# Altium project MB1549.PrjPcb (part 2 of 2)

## Sheet POWER_BOARD.SchDoc: POWER_BOARD
size A4; Date: Not used; ApprovedBy: Not used; CheckedBy: Not used; Author: Not used; CompanyName: STMicroelectronics; DrawnBy: Not used; Engineer: Not used; Organization: Not used; Address1: Not used; Address2: Not used; Address3: Not used; Address4: Not used; DocumentNumber: 7; Revision: Not used; SheetNumber: 7; SheetTotal: 8
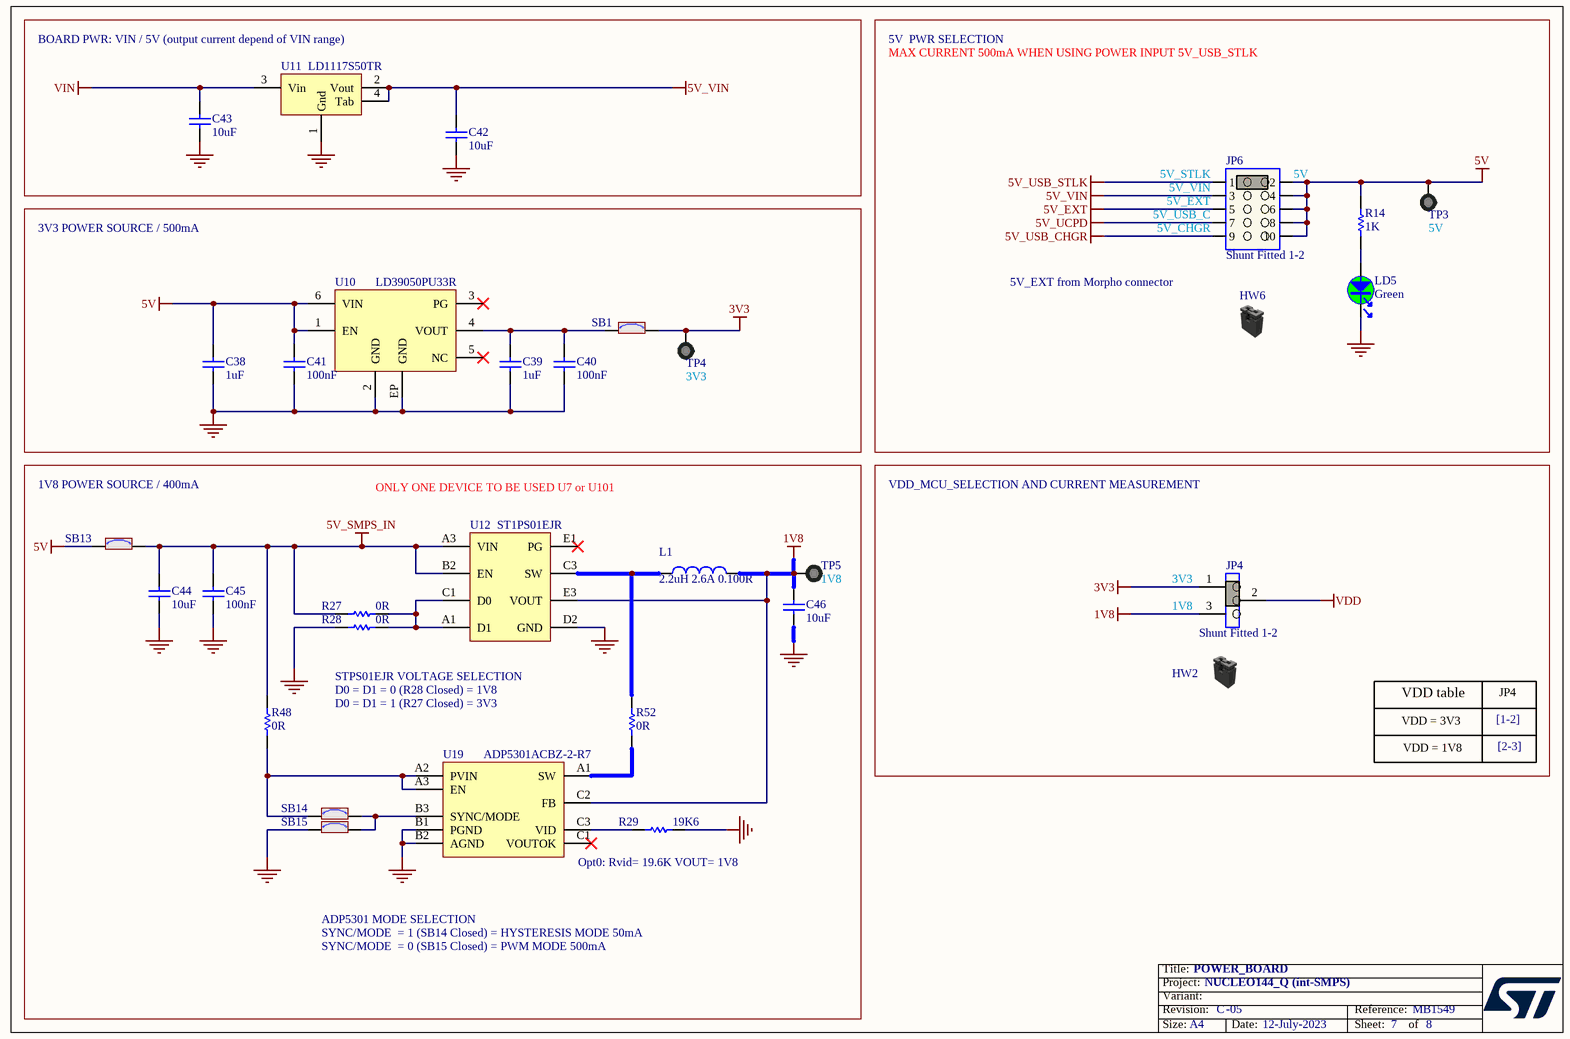
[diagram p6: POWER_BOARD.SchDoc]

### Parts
C38  value 1uF  [C0603]  (hidden comment: Capacitor)
C39  value 1uF  [C0603]  (hidden comment: Capacitor)
C40  value 100nF  [C0402]
C41  value 100nF  [C0402]
C42  value 10uF  [C0805]
C43  value 10uF  [C0805]
C44  value 10uF  [C0603]
C45  value 100nF  [C0402]
C46  value 10uF  [C0603]
HW2  (no value)  (mechanical)
HW6  (no value)  (mechanical)
JP4  value Shunt Fitted 1-2  [CON_SAMTEC_TSW-103-07-F-S]
JP6  value Shunt Fitted 1-2  [CON_SAMTEC_TSW-105-07-X-D]
L1  value 2.2uH 2.6A 0.100R  [IND_TDK_VLS252010HBX-1]
LD5  value Green  [LED_0603_GREEN]  (hidden comment: LED_green)
R14  value 1K  [R0603]
R27  value 0R  [R0603]
R28  value 0R  [R0603]
R29  value 19K6  [R0603]
R48  value 0R  [R0603]
R52  value 0R  [R0603]
SB1  (no value)  [SOLDER-BRIDGE_R0603-0R]
SB13  (no value)  [SOLDER-BRIDGE_R0603-0R]
SB14  (no value)  [SOLDER-BRIDGE_R0603-0R]
SB15  (no value)  [SOLDER-BRIDGE_R0603-0R]
TP3  Test_Point_PTH_1mm_2mm  [TP_PTH_1MM_2MM]  (value not drawn)  (no BOM)
TP4  Test_Point_PTH_1mm_2mm  [TP_PTH_1MM_2MM]  (value not drawn)  (no BOM)
TP5  Test_Point_PTH_1mm_2mm  [TP_PTH_1MM_2MM]  (value not drawn)  (no BOM)
U10  value LD39050PU33R  [ICC_DFN6-EPAD_3X3_P095]
U11  value LD1117S50TR  [REG_SOT223-TAB]
U12  value ST1PS01EJR  [ICC_FLIP-CHIP-BGA8_1P11X1P41_P040]
U19  value ADP5301ACBZ-2-R7  [ICC_WLCSP9_1P65X1P87_P050]

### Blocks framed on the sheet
BOARD PWR: VIN / 5V (output current depend of VIN range): C42 C43 U11
VDD table: HW2 JP4

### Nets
1V8: C46.2 JP4.3 L1.2 TP5.1 U12.E3(VOUT) U19.C2(FB)
3V3: JP4.1 SB1.2 TP4.1
5V: C38.2 C41.2 JP6.2 JP6.4 JP6.6 JP6.8 JP6.10 R14.2 SB13.1 TP3.1 U10.1(EN) U10.6(VIN)
5V_EXT: JP6.5
5V_SMPS_IN: C44.2 C45.2 R27.2 R48.1 SB13.2 U12.A3(VIN) U12.B2(EN)
5V_UCPD: JP6.7
5V_USB_CHGR: JP6.9
5V_USB_STLK: JP6.1
5V_VIN: C42.2 JP6.3 U11.2(Vout) U11.4(Tab)
GND: C38.1 C39.1 C40.1 C41.1 C42.1 C43.1 C44.1 C45.1 C46.1 LD5.2 R28.2 R29.2 SB15.1 U10.2(GND) U10.EP(GND) U11.1(Gnd) U12.D2(GND) U19.B1(PGND) U19.B2(AGND)
VDD: JP4.2
VIN: C43.2 U11.3(Vin)
NetC39_2: C39.2 C40.2 SB1.1 U10.4(VOUT)
NetL1_1: L1.1 R52.1 U12.C3(SW)
NetLD5_1: LD5.1 R14.1
NetR27_1: R27.1 R28.1 U12.A1(D1) U12.C1(D0)
NetR29_1: R29.1 U19.C3(VID)
NetR48_2: R48.2 SB14.1 U19.A2(PVIN) U19.A3(EN)
NetR52_2: R52.2 U19.A1(SW)
NetSB14_2: SB14.2 SB15.2 U19.B3(SYNC/MODE)

Not connected (* = marked no-connect by the designer): U10 3(PG)* 5(NC)*; U12 E1(PG)*; U19 C1(VOUTOK)*

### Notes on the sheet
- 5V  PWR SELECTION
- MAX CURRENT 500mA WHEN USING POWER INPUT 5V_USB_STLK
- (near JP6) 5V_STLK
- (near JP6) 5V
- 3V3 POWER SOURCE / 500mA
- (near JP6) 5V_CHGR
- (near JP6) 5V_VIN
- (near JP6) 5V_EXT
- (near JP6) 5V_USB_C
- (near TP3) 5V
- 5V_EXT from Morpho connector
- (near TP4) 3V3
- 1V8 POWER SOURCE / 400mA
- ONLY ONE DEVICE TO BE USED U7 or U101
- VDD_MCU_SELECTION AND CURRENT MEASUREMENT
- (near TP5) 1V8
- (near JP4) 3V3
- 1V8
- STPS01EJR VOLTAGE SELECTION
  D0 = D1 = 0 (R28 Closed) = 1V8
  D0 = D1 = 1 (R27 Closed) = 3V3
- [1-2]
- JP4
- VDD = 3V3
- VDD = 1V8
- [2-3]
- Opt0: Rvid= 19.6K VOUT= 1V8
- ADP5301 MODE SELECTION
  SYNC/MODE  = 1 (SB14 Closed) = HYSTERESIS MODE 50mA
  SYNC/MODE  = 0 (SB15 Closed) = PWM MODE 500mA

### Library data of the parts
C38 C39 = MCD-00010: Capacitor, MLCC, 1uF, 16V, X5R, 10%, 0603, T=0,8mm; Manufacturer_Part_Number: CC0603KRX5R7BB105; Manufacturer: YAGEO; Provided_By: SUBCO
C40 C41 C45 = MCD-00006: Capacitor, MLCC, 100nF, 16V, X7R, 10%, 0402, T=0.5mm; Manufacturer_Part_Number: CC0402KRX7R7BB104; Manufacturer: YAGEO; Alternate_Manufacturer_Part_Number: GCM155R71C104KA55D; Alternate_Manufacturer: MURATA; Provided_By: SUBCO; ECCN_US: EAR99; ECCN_EU: NEC
C42 C43 = MCD-00014: Capacitor, MLCC, 10uF, 25V, X5R, 10%, 0805, T=0,85mm; Manufacturer_Part_Number: CC0805KRX5R8BB106; Manufacturer: YAGEO; Provided_By: Subcon; Initial_Board_Reference: MB1274
C44 C46 = MCD-00243: Capacitor, MLCC, 10uF, 6V3, X5R, 10%, 0603, T=0,8mm; Manufacturer_Part_Number: CC0603KRX5R5BB106; Manufacturer: YAGEO; Provided_By: Subcon; Initial_Board_Reference: MB1319
HW2 HW6 = MCD-00043: SHUNT 2.54mm BLACK; Manufacturer_Part_Number: SNT-100-BK-G; Manufacturer: SAMTEC; Part_Type: Mechanical; Provided_By: Subcon; Initial_Board_Reference: MB1274
JP4 = MCD-00684: Header, 3x1, 2,54mm, VR, TH, Height 5.84mm/2.54mm - Shunt Fitted 1-2 by default; Part_Type: Connector; Manufacturer_Part_Number: TSW-103-07-F-S; Manufacturer: SAMTEC; Provided_By: Subcon; Initial_Board_Reference: MB1331
JP6 = MCD-01203: Header, 5x2, 2,54mm, VR, TH, Height 5.84mm/2.54mm - Shunt Fitted 1-2; Part_Type: Connector; Manufacturer_Part_Number: TSW-105-07-x-D; Manufacturer: SAMTEC; Provided_By: Subcon; Initial_Board_Reference: Mb1372
L1 = MCD-00240: FIXED IND 2.2UH 2.6A 100 mOHM 20% SMD; Manufacturer_Part_Number: VLS252010HBX-2R2M-1; Manufacturer: TDK; Provided_By: Subcon; Initial_Board_Reference: MB1319
LD5 = MCD-02900: LED, Green, 2V, 20mA, 0603; Part_Type: Display; Part_Preference: Recommended; Manufacturer: EVERLIGHT; Manufacturer_Part_Number: 19-213SYGC/S530-E2/5T; Full_Alternate_Internal_Part_Number: MCD-00320; Partial_Alternate_Internal_Part_Number: MCD-00050; Component_Country_Of_Origin: China; ShowFields: YES; ID: 5016
R14 = MCD-00070: Resistor,1K,0603,1%,1/10W; Manufacturer_Part_Number: RC0603FR-071KL; Manufacturer: YAGEO; Provided_By: Subcon; Initial_Board_Reference: MB1274
R27 R28 R48 R52 = MCD-00056: Resistor,0R,0603,5%,1/10W; Manufacturer_Part_Number: RC0603JR-070RL; Manufacturer: YAGEO; Provided_By: subcon; Initial_Board_Reference: MB1274
R29 = MCD-00242: Resistor,19K6,0603,1%,1/10W; Manufacturer_Part_Number: RC0603FR-0719K6L; Manufacturer: YAGEO; Provided_By: Subcon; Initial_Board_Reference: MB1319
SB1 SB13-SB15 = MCD-00071: Solder Bridge ON; Part_Type: Mechanical; Provided_By: Subcon; Initial_Board_Reference: MB1274
TP3-TP5 = MCD-01506: Test Point trought hole 1mm/2mm; Part_Type: Mechanical; Value: TP
U10 = MCD-00215: Low quiescent current and low noise voltage regulators; Manufacturer: STMICROELECTRONICS; Part_Type: IC; ECCN_US: EAR99; ECCN_EU: NEC; Provided_By: Subcon; Initial_Board_Reference: MB1319
U11 = MCD-00088: IC REG LDO 5V 0.8A SOT223; Manufacturer: STMICROELECTRONICS; ECCN_US: EAR99; ECCN_EU: NEC; Provided_By: Subcon; Initial_Board_Reference: MB1274
U12 = MCD-00228: 400mA Nano-Quiescent Step down converter; Manufacturer: STMICROELECTRONICS; Part_Type: IC; ECCN_US: EAR99; ECCN_EU: NEC; Provided_By: Subcon; Initial_Board_Reference: MB1319
U19 = MCD-00226: UL Step down regulator: Opt0; Manufacturer: ANALOG DEVICES; Part_Type: IC; ECCN_US: EAR99; ECCN_EU: NEC; Provided_By: Subcon; Initial_Board_Reference: MB1319

## Sheet ST_LINK_V3E.SchDoc: STLINK_V3E
size A3; Date: Not used; ApprovedBy: Not used; CheckedBy: Not used; Author: Not used; CompanyName: STMicroelectronics; DrawnBy: Not used; Engineer: Not used; Organization: Not used; Address1: Not used; Address2: Not used; Address3: Not used; Address4: Not used; DocumentNumber: 8; Revision: Not used; SheetNumber: 8; SheetTotal: 8
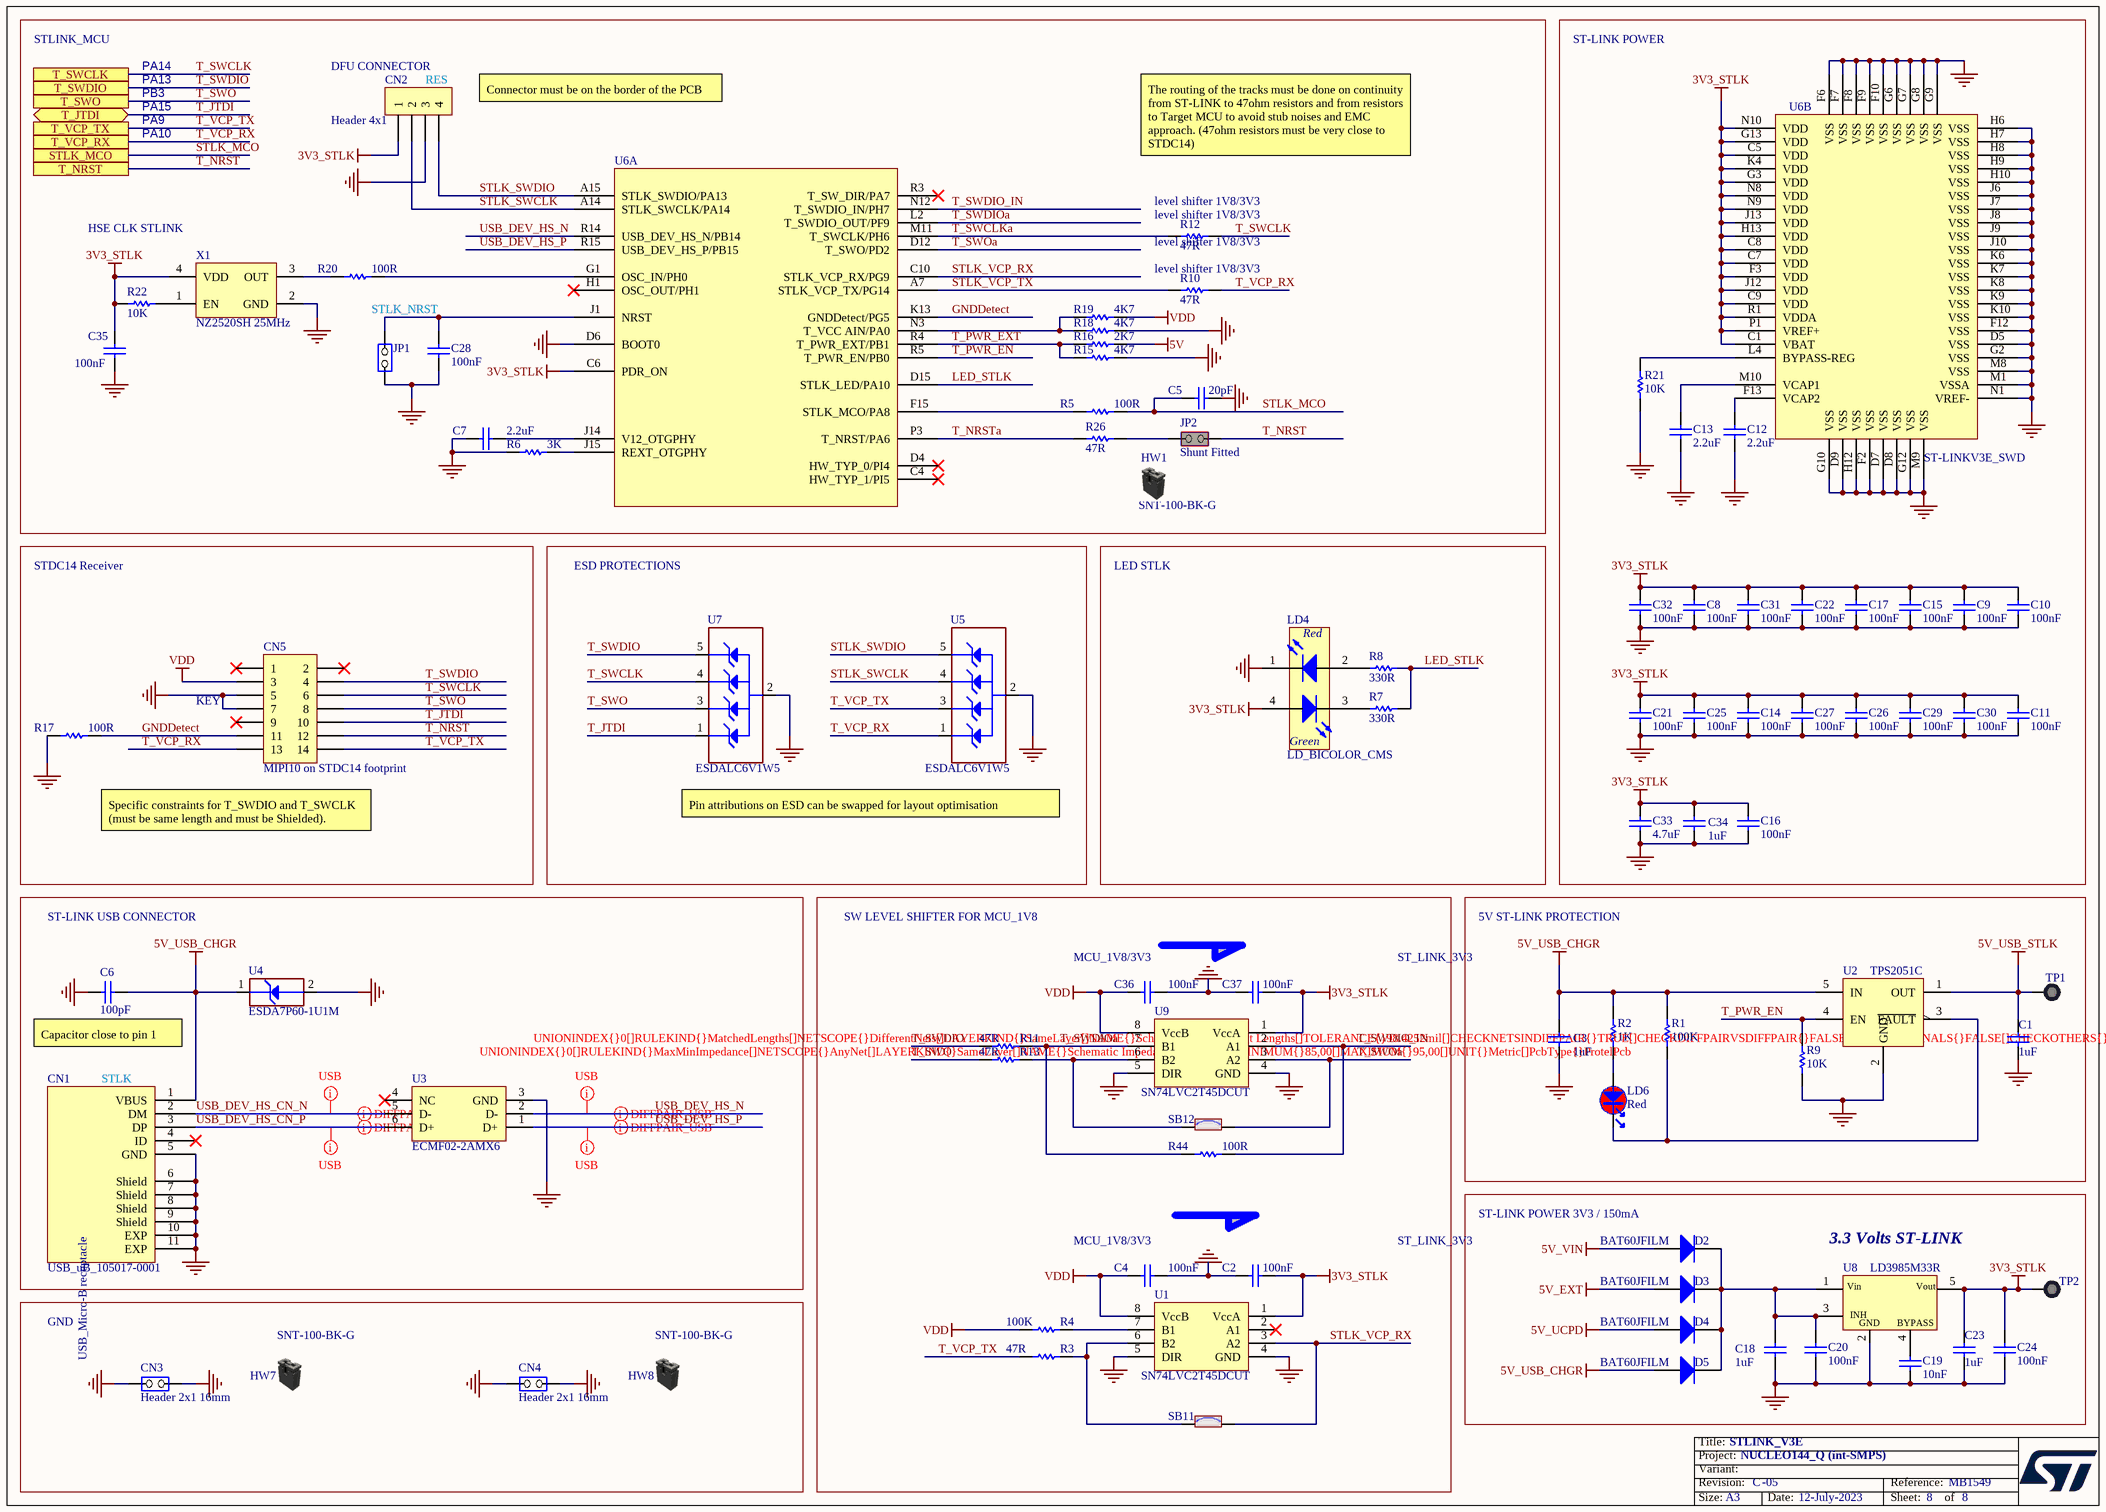
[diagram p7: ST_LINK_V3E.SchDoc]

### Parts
C1  value 1uF  [C0603]  (hidden comment: Capacitor)
C2  value 100nF  [C0402]
C3  value 1uF  [C0603]  (hidden comment: Capacitor)
C4  value 100nF  [C0402]
C5  value 20pF  [C0402]  (hidden comment: Capacitor)
C6  value 100pF  [C0402]  (hidden comment: Capacitor)
C7  value 2.2uF  [C0603]  (hidden comment: Capacitor)
C8  value 100nF  [C0402]
C9  value 100nF  [C0402]
C10  value 100nF  [C0402]
C11  value 100nF  [C0402]
C12  value 2.2uF  [C0603]  (hidden comment: Capacitor)
C13  value 2.2uF  [C0603]  (hidden comment: Capacitor)
C14  value 100nF  [C0402]
C15  value 100nF  [C0402]
C16  value 100nF  [C0402]
C17  value 100nF  [C0402]
C18  value 1uF  [C0603]  (hidden comment: Capacitor)
C19  value 10nF  [C0402]  (hidden comment: Capacitor)
C20  value 100nF  [C0402]
C21  value 100nF  [C0402]
C22  value 100nF  [C0402]
C23  value 1uF  [C0603]  (hidden comment: Capacitor)
C24  value 100nF  [C0402]
C25  value 100nF  [C0402]
C26  value 100nF  [C0402]
C27  value 100nF  [C0402]
C28  value 100nF  [C0402]
C29  value 100nF  [C0402]
C30  value 100nF  [C0402]
C31  value 100nF  [C0402]
C32  value 100nF  [C0402]
C33  value 4.7uF  [C0603]  (hidden comment: Capacitor)
C34  value 1uF  [C0603]  (hidden comment: Capacitor)
C35  value 100nF  [C0402]
C36  value 100nF  [C0402]
C37  value 100nF  [C0402]
CN1  value USB_uB_105017-0001  [CON_USBMICROB_MOLEX_105017-0001_H2P90]  (hidden comment: USB_uB_105017.0001)
CN2  Header 4x1  [CON_SAMTEC_TSW-104-07-G-S]
CN3  value Header 2x1 16mm  [CON_SAMTEC_TSW-102-09-X-S]  (hidden comment: Jumper_Header 2x1)
CN4  value Header 2x1 16mm  [CON_SAMTEC_TSW-102-09-X-S]  (hidden comment: Jumper_Header 2x1)
CN5  value MIPI10 on STDC14 footprint  [CON_STDC14_Receiver_MEDIUM_WITH_MIPI10_3D]  (hidden comment: Header 7x2)
D2  BAT60JFILM  [DIO_SOD323]
D3  BAT60JFILM  [DIO_SOD323]
D4  BAT60JFILM  [DIO_SOD323]
D5  BAT60JFILM  [DIO_SOD323]
HW1  value SNT-100-BK-G  (hidden comment: Shunt Black 2.54mm)  (mechanical)
HW7  value SNT-100-BK-G  (hidden comment: Shunt Black 2.54mm)  (mechanical)
HW8  value SNT-100-BK-G  (hidden comment: Shunt Black 2.54mm)  (mechanical)
JP1  Jumper_Header 2x1  [CON_SAMTEC_TSW-102-07-G-S]  (value not drawn)
JP2  value Shunt Fitted  [CON_SAMTEC_TSW-102-07-G-S]  (hidden comment: Jumper_Header 2x1 Fitted)
LD4  LD_BICOLOR_CMS  [LED_BI-GR_HSMF-A201-A00J1]
LD6  value Red  [LED_0603_RED]  (hidden comment: LED_red)
R1  value 100K  [R0603]  (hidden comment: Resistor)
R2  value 1K  [R0603]  (hidden comment: Resistor)
R3  value 47R  [R0402]  (hidden comment: Resistor)
R4  value 100K  [R0603]  (hidden comment: Resistor)
R5  value 100R  [R0402]  (hidden comment: Resistor)
R6  value 3K  [R0402]  (hidden comment: Resistor)
R7  value 330R  [R0603]  (hidden comment: Resistor)
R8  value 330R  [R0603]  (hidden comment: Resistor)
R9  value 10K  [R0402]  (hidden comment: Resistor)
R10  value 47R  [R0402]  (hidden comment: Resistor)
R11  value 47R  [R0402]  (hidden comment: Resistor)
R12  value 47R  [R0402]  (hidden comment: Resistor)
R13  value 47R  [R0402]  (hidden comment: Resistor)
R15  value 4K7  [R0402]  (hidden comment: Resistor)
R16  value 2K7  [R0402]  (hidden comment: Resistor)
R17  value 100R  [R0402]  (hidden comment: Resistor)
R18  value 4K7  [R0402]  (hidden comment: Resistor)
R19  value 4K7  [R0402]  (hidden comment: Resistor)
R20  value 100R  [R0402]  (hidden comment: Resistor)
R21  value 10K  [R0402]  (hidden comment: Resistor)
R22  value 10K  [R0402]  (hidden comment: Resistor)
R26  value 47R  [R0402]  (hidden comment: Resistor)
R44  value 100R  [R0402]  (hidden comment: Resistor)
SB11  SB_ON  [SOLDER-BRIDGE_R0603-0R]  (value not drawn)
SB12  SB_ON  [SOLDER-BRIDGE_R0603-0R]  (value not drawn)
TP1  Test_Point_PTH_1mm_2mm  [TP_PTH_1MM_2MM]  (value not drawn)  (no BOM)
TP2  Test_Point_PTH_1mm_2mm  [TP_PTH_1MM_2MM]  (value not drawn)  (no BOM)
U1  SN74LVC2T45DCUT  [ICC_VSSOP8_DCU_R-PDSO-G8_2X2P30_P050]
U2  TPS2051C  [MOS_SOT23-5L]
U3  ECMF02-2AMX6  [ESD_QFN-6L_1P7X1P5_P050]
U4  value ESDA7P60-1U1M  [ESD_QFN2_1P6X1_P125]  (hidden comment: ESD-TRANSIL)
U5  ESDALC6V1W5  [ESD_SOT323-5L]
U6  ST-LINKV3E_SWD  [ICC_UFBGA201_176+25_10X10_P065]  (parts A,B of 2)
U7  ESDALC6V1W5  [ESD_SOT323-5L]
U8  LD3985M33R  [REG_SOT23-5L]
U9  SN74LVC2T45DCUT  [ICC_VSSOP8_DCU_R-PDSO-G8_2X2P30_P050]
X1  value NZ2520SH 25MHz  [OSC_NDK_NZ2520SB_4P]  (hidden comment: OSCILLATOR_4_PINS)

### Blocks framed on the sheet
ST-LINK POWER: C8-C17 C21 C22 C25-C27 C29-C34 R21 U6
ESD PROTECTIONS: U5 U7
LED STLK: LD4 R7 R8
5V ST-LINK PROTECTION: C1 C3 LD6 R1 R2 R9 TP1 U2
3.3 Volts ST-LINK: C18-C20 C23 C24 D2-D5 TP2 U8
GND: CN3 CN4 HW7 HW8

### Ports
STLK_MCO, T_JTDI (bidir), T_NRST, T_SWCLK, T_SWDIO, T_SWO, T_VCP_RX, T_VCP_TX

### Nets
3V3_STLK: C2.2 C8.2 C9.2 C10.2 C11.2 C14.2 C15.2 C16.2 C17.2 C21.2 C22.2 C23.2 C24.2 C25.2 C26.2 C27.2 C29.2 C30.2 C31.2 C32.2 C33.2 C34.2 C35.2 C37.2 CN2.1 LD4.4(YellowGreen_anode) R22.2 TP2.1 U1.1(VccA) U6.C1(VBAT) U6.C5(VDD) U6.C6(PDR_ON) U6.C7(VDD) U6.C8(VDD) U6.C9(VDD) U6.F3(VDD) U6.G3(VDD) U6.G13(VDD) U6.H13(VDD) U6.J12(VDD) U6.J13(VDD) U6.K4(VDD) U6.N8(VDD) U6.N9(VDD) U6.N10(VDD) U6.P1(VREF+) U6.R1(VDDA) U8.5(Vout) U9.1(VccA) X1.4(VDD)
5V: R16.1
5V_EXT: D3.1(A)
5V_UCPD: D4.1(A)
5V_USB_CHGR: C3.2 C6.2 CN1.1(VBUS) D5.1(A) R1.2 R2.2 U2.5(IN) U4.1(IO1)
5V_USB_STLK: C1.2 TP1.1 U2.1(OUT)
5V_VIN: D2.1(A)
GND: C1.1 C2.1 C3.1 C4.2 C5.1 C6.1 C7.1 C8.1 C9.1 C10.1 C11.1 C12.1 C13.1 C14.1 C15.1 C16.1 C17.1 C18.1 C19.1 C20.1 C21.1 C22.1 C23.1 C24.1 C25.1 C26.1 C27.1 C28.1 C29.1 C30.1 C31.1 C32.1 C33.1 C34.1 C35.1 C36.2 C37.1 CN1.5(GND) CN1.6(Shield) CN1.7(Shield) CN1.8(Shield) CN1.9(Shield) CN1.10(EXP) CN1.11(EXP) CN2.3 CN3.1(COMMON) CN3.2(NO) CN4.1(COMMON) CN4.2(NO) CN5.5 CN5.7 JP1.1(COMMON) LD4.1(RED_cathode) R6.1 R9.2 R15.1 R17.1 R18.2 R21.1 U1.4(GND) U1.5(DIR) U2.2(GND) U3.3(GND) U4.2(GND) U5.2(GND) U6.D5(VSS) U6.D6(BOOT0) U6.D7(VSS) U6.D8(VSS) U6.D9(VSS) U6.F2(VSS) U6.F6(VSS) U6.F7(VSS) U6.F8(VSS) U6.F9(VSS) U6.F10(VSS) U6.F12(VSS) U6.G2(VSS) U6.G6(VSS) U6.G7(VSS) U6.G8(VSS) U6.G9(VSS) U6.G10(VSS) U6.G12(VSS) U6.H6(VSS) U6.H7(VSS) U6.H8(VSS) U6.H9(VSS) U6.H10(VSS) U6.H12(VSS) U6.J6(VSS) U6.J7(VSS) U6.J8(VSS) U6.J9(VSS) U6.J10(VSS) U6.K6(VSS) U6.K7(VSS) U6.K8(VSS) U6.K9(VSS) U6.K10(VSS) U6.M1(VSSA) U6.M8(VSS) U6.M9(VSS) U6.N1(VREF-) U7.2(GND) U8.2(GND) U9.4(GND) U9.5(DIR) X1.2(GND)
VDD: C4.1 C36.1 CN5.3 R4.2 R19.2 U1.8(VccB) U9.8(VccB)
GNDDetect: CN5.11 R17.2 U6.K13(GNDDetect/PG5)
LED_STLK: R7.2 R8.2 U6.D15(STLK_LED/PA10)
STLK_MCO: C5.2 R5.2 ; port STLK_MCO
STLK_SWCLK: CN2.2 U5.4(IO3) U6.A14(STLK_SWCLK/PA14)
STLK_SWDIO: CN2.4 U5.5(IO4) U6.A15(STLK_SWDIO/PA13)
STLK_VCP_RX: SB11.1 U1.3(A2) U6.C10(STLK_VCP_RX/PG9)
STLK_VCP_TX: R10.1 U6.A7(STLK_VCP_TX/PG14)
T_JTDI: CN5.10 U7.1(IO1) ; port T_JTDI
T_NRST: CN5.12 JP2.2(NO) ; port T_NRST
T_NRSTa: R26.1 U6.P3(T_NRST/PA6)
T_PWR_EN: R9.1 U2.4(EN) U6.R5(T_PWR_EN/PB0)
T_PWR_EXT: R15.2 R16.2 U6.R4(T_PWR_EXT/PB1)
T_SWCLK: CN5.6 R12.2 U7.4(IO3) ; port T_SWCLK  [project net PA14]
T_SWCLKa: R12.1 U6.M11(T_SWCLK/PH6)
T_SWDIO: CN5.4 R11.1 U7.5(IO4) ; port T_SWDIO  [project net PA13]
T_SWDIO_IN: R44.2 U6.N12(T_SWDIO_IN/PH7) U9.2(A1)
T_SWDIOa: R11.2 R44.1 U6.L2(T_SWDIO_OUT/PF9) U9.7(B1)
T_SWO: CN5.8 R13.1 U7.3(IO2) ; port T_SWO
T_SWOa: SB12.1 U6.D12(T_SWO/PD2) U9.3(A2)
T_VCP_RX: CN5.13 R10.2 U5.1(IO1) ; port T_VCP_RX
T_VCP_TX: CN5.14 R3.1 U5.3(IO2) ; port T_VCP_TX
USB_DEV_HS_CN_N: CN1.2(DM) U3.5(D-)
USB_DEV_HS_CN_P: CN1.3(DP) U3.6(D+)
USB_DEV_HS_N: U3.2(D-) U6.R14(USB_DEV_HS_N/PB14)
USB_DEV_HS_P: U3.1(D+) U6.R15(USB_DEV_HS_P/PB15)
NetC7_2: C7.2 U6.J14(V12_OTGPHY)
NetC12_2: C12.2 U6.F13(VCAP2)
NetC13_2: C13.2 U6.M10(VCAP1)
NetC18_2: C18.2 C20.2 D2.2(K) D3.2(K) D4.2(K) D5.2(K) U8.1(Vin) U8.3(CE)
NetC19_2: C19.2 U8.4(BYPASS)
NetC28_2: C28.2 JP1.2(NO) U6.J1(NRST)
NetJP2_1: JP2.1(COMMON) R26.2
NetLD4_2: LD4.2(Red_anode) R8.1
NetLD4_3: LD4.3(YellowGreen_cathode) R7.1
NetLD6_1: LD6.1 R2.1
NetLD6_2: LD6.2 R1.1 U2.3(~{FAULT})
NetR3_2: R3.2 SB11.2 U1.6(B2)
NetR4_1: R4.1 U1.7(B1)
NetR5_1: R5.1 U6.F15(STLK_MCO/PA8)
NetR6_2: R6.2 U6.J15(REXT_OTGPHY)
NetR13_2: R13.2 SB12.2 U9.6(B2)
NetR18_1: R18.1 R19.1 U6.N3(T_VCC_AIN/PA0)
NetR20_1: R20.1 X1.3(OUT)
NetR20_2: R20.2 U6.G1(OSC_IN/PH0)
NetR21_2: R21.2 U6.L4(BYPASS-REG)
NetR22_1: R22.1 X1.1(EN)

Not connected (* = marked no-connect by the designer): CN1 4(ID)*; CN5 1* 2* 9*; U1 2(A1)*; U3 4(NC)*; U6 C4(HW_TYP_1/PI5)* D4(HW_TYP_0/PI4)* H1(OSC_OUT/PH1)* R3(T_SW_DIR/PA7)*

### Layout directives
differential pair; rule Impedance Constraint [Min = 85.00    Max = 95.00    ]: USB_DEV_HS_CN_N, USB_DEV_HS_CN_P, USB_DEV_HS_N, USB_DEV_HS_P
rule Undefined; rule Matched Net Lengths [Tolerance = 2.5mm]; rule Impedance Constraint [Min = 85.00    Max = 95.00    ]: USB_DEV_HS_N
rule Undefined; rule Matched Net Lengths [Tolerance = 0.2mm]; rule Impedance Constraint [Min = 85.00    Max = 95.00    ]: USB_DEV_HS_CN_N, USB_DEV_HS_CN_P, USB_DEV_HS_P

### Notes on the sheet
- STLINK_MCU
- PA14
- PA13
- PB3
- PA15
- (near CN2) DFU CONNECTOR
- (near CN2) RES
- (near CN2) Connector must be on the border of the PCB
- PA9
- PA10
- The routing of the tracks must be done on continuity from ST-LINK to 47ohm resistors and from resistors to Target MCU to avoid stub noises and EMC approach. (47ohm resistors must be very close to STDC14)
- HSE CLK STLINK
- (near R12) level shifter 1V8/3V3
- STLK_NRST
- level shifter 1V8/3V3
- STDC14 Receiver
- (near CN5) KEY
- Specific constraints for T_SWDIO and T_SWCLK (must be same length and must be Shielded).
- Pin attributions on ESD can be swapped for layout optimisation
- ST-LINK USB CONNECTOR
- SW LEVEL SHIFTER FOR MCU_1V8
- MCU_1V8/3V3
- ST_LINK_3V3
- (near C6) Capacitor close to pin 1
- (near CN1) STLK
- ST-LINK POWER 3V3 / 150mA

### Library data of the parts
C1 C3 C18 C23 C34 = MCD-00010: Capacitor, MLCC, 1uF, 16V, X5R, 10%, 0603, T=0,8mm; Manufacturer_Part_Number: CC0603KRX5R7BB105; Manufacturer: YAGEO; Provided_By: SUBCO; ECCN_US: EAR99; ECCN_EU: NEC
C2 C4 C8-C11 C14-C17 C20-C22 C24-C32 C35-C37 = MCD-00006: as C40 on sheet POWER_BOARD
C5 = MCD-00016: Capacitor, MLCC, 20pF, 50V, NPO, 5%, 0402, T=0,5mm; Manufacturer_Part_Number: CC0402JRNPO9BN200; Manufacturer: YAGEO; Provided_By: SUBCO; ECCN_US: EAR99; ECCN_EU: NEC
C6 = MCD-00205: Capacitor, MLCC, 100pF, 50V, NPO, 5%, 0402, T=0,5mm; Manufacturer_Part_Number: CC0402JRNPO9BN101; Manufacturer: YAGEO; Provided_By: SUBCO; ECCN_US: EAR99; ECCN_EU: NEC
C7 C12 C13 = MCD-00012: Capacitor, MLCC, 2.2uF, 10V, X5R, 10%, 0603, T=0,8mm; Manufacturer_Part_Number: CC0603KRX5R6BB225; Manufacturer: YAGEO; Alternate_Manufacturer_Part_Number: C0603C225K8PACTU; Alternate_Manufacturer: KEMET; Provided_By: SUBCO; ECCN_US: EAR99; ECCN_EU: NEC
C19 = MCD-00011: Capacitor, MLCC, 10nF, 16V, X7R, 10%, 0402, T=0.5mm; Manufacturer_Part_Number: CC0402KRX7R7BB103; Manufacturer: YAGEO; Provided_By: SUBCO; ECCN_US: EAR99; ECCN_EU: NEC
C33 = MCD-00009: Capacitor, MLCC, 4.7uF, 16V, X5R, 10%, 0603, T=0.8mm; Manufacturer_Part_Number: CC0603KRX5R7BB475; Manufacturer: YAGEO; Provided_By: SUBCO; ECCN_US: EAR99; ECCN_EU: NEC
CN1 = MCD-00028: USB-MICRO-B, 0.65mm, RA, SMT, Bottom Mount,; Manufacturer_Part_Number: 1050170001; Manufacturer: MOLEX; Part_Type: Connector; Provided_By: SUBCO
CN2 = MCD-00029: Header, 4x1, 2,54mm, VR, TH, Height 5.84mm/2.54mm; Manufacturer_Part_Number: TSW-104-07-x-S; Manufacturer: SAMTEC; Part_Type: Connector; Provided_By: SUBCO
CN3 CN4 = MCD-00214: Header, 2x1, 2,54mm, VR, TH, Height 5.84mm/10.16mm; Part_Type: Connector; Manufacturer_Part_Number: TSW-102-09-x-S; Manufacturer: SAMTEC; Provided_By: SUBCO
CN5 = MCD-01226: Header 5x2, 1.27mm, Dual row, Straight, Surface mount, vertical male connector. 3.05mm lead. Mates with FFSD connector. Footprint compatible with FTSH-107-01-L-DV,-K,-A,-P,-ES (STDC14 MEDIUM); Manufacturer_Part_Number: FTSH-105-01-L-DV-K; Manufacturer: SAMTEC; Alternate_Manufacturer_Part_Number: P127B-2x05MGF-079-1A; Alternate_Manufacturer: JIUBABA; Provided_By: SUBCO
D2-D5 = MCD-00034: Manufacturer: STMICROELECTRONICS; Part_Type: Diode; BMS_Part_Number: 9151097; Provided_By: SUBCO with ST control; ECCN_US: EAR99; ECCN_EU: NEC
HW1 HW7 HW8 = MCD-00043: SHUNT 2.54mm BLACK; Manufacturer: SAMTEC; Part_Type: Mechanical; Alternate_Manufacturer_Part_Number: 316102S111A; Alternate_Manufacturer: JIUBABA; Provided_By: SUBCO
JP1 = MCD-00045: Header, 2x1, 2,54mm, VR, TH, Height 5.84mm/2.54mm; Part_Type: Connector; Manufacturer_Part_Number: TSW-102-07-x-S; Manufacturer: SAMTEC; Alternate_Manufacturer_Part_Number: 313102S111116;313102S111116; Alternate_Manufacturer: JIUBABA; LIANYI; Value: Shunt not fitted; Provided_By: SUBCO
JP2 = MCD-00683: Header, 2x1, 2,54mm, VR, TH, Height 5.84mm/2.54mm - Shunt Fitted by default; Part_Type: Connector; Manufacturer_Part_Number: TSW-102-07-x-S; Manufacturer: SAMTEC; Alternate_Manufacturer_Part_Number: 313102S111116; Alternate_Manufacturer: LIANYI; Provided_By: SUBCO
LD4 = MCD-02402: LED Bicolor; Part_Type: Display; Part_Preference: Alternate; Manufacturer: EVERLIGHT; Manufacturer_Part_Number: 67-22sursygc-s530-a2-tr8; Full_Alternate_Internal_Part_Number: MCD-00051, MCD-02631; Alternate_EMS: C; ShowFields: YES; ID: 4508
LD6 = MCD-02899: LED, Red, 2V35, 20mA, 0603; Part_Type: Display; Part_Preference: Recommended; Manufacturer: EVERLIGHT; Manufacturer_Part_Number: 19-213/R6C-AP1Q2B/5T; Full_Alternate_Internal_Part_Number: MCD-00049; Component_Country_Of_Origin: China; ShowFields: YES; ID: 5015
R1 R4 = MCD-00223: Resistor,100K,0603,1%,1/10W; Manufacturer_Part_Number: RC0603FR-07100KL; Manufacturer: YAGEO; Provided_By: SUBCO; ECCN_US: EAR99; ECCN_EU: NEC
R2 = MCD-00070: Resistor,1K,0603,1%,1/10W; Manufacturer_Part_Number: RC0603FR-071KL; Manufacturer: YAGEO; Provided_By: SUBCO; ECCN_US: EAR99; ECCN_EU: NEC
R3 R10-R13 R26 = MCD-00481: Resistor,47R,0402,1%,1/16W; Manufacturer_Part_Number: RC0402FR-0747RL; Manufacturer: YAGEO; Provided_By: SUBCO; ECCN_US: EAR99; ECCN_EU: NEC
R5 R17 R20 R44 = MCD-00067: Resistor,100R,0402,1%,1/16W; Manufacturer_Part_Number: RC0402FR-07100RL; Manufacturer: YAGEO; ECCN_US: EAR99; ECCN_EU: NEC; Provided_By: SUBCO
R6 = MCD-00185: Resistor,3K,0402,1%,1/16W; Manufacturer_Part_Number: RC0402FR-073KL; Manufacturer: YAGEO; Provided_By: SUBCO; ECCN_US: EAR99; ECCN_EU: NEC
R7 R8 = MCD-00197: Resistor,330R,0603,1%,1/10W; Manufacturer_Part_Number: RC0603FR-07330RL; Manufacturer: YAGEO; BMS_Part_Number: 9129729; Provided_By: SUBCO; ECCN_US: EAR99; ECCN_EU: NEC
R9 R21 R22 = MCD-00053: Resistor,10K,0402,1%,1/16W; Manufacturer_Part_Number: RC0402FR-0710KL; Manufacturer: YAGEO; ECCN_US: EAR99; ECCN_EU: NEC; Provided_By: SUBCO
R15 R18 R19 = MCD-00065: Resistor,4K7,0402,1%,1/16W; Manufacturer_Part_Number: RC0402FR-074K7L; Manufacturer: YAGEO; Alternate_Manufacturer_Part_Number: RT0402FRE074K7L; Provided_By: SUBCO; ECCN_US: EAR99; ECCN_EU: NEC
R16 = MCD-00055: Resistor,2K7,0402,1%,1/16W; Manufacturer_Part_Number: RC0402FR-072K7L; Manufacturer: YAGEO; Provided_By: SUBCO; ECCN_US: EAR99; ECCN_EU: NEC
SB11 SB12 = MCD-00071: Solder Bridge ON; Part_Type: Mechanical; Manufacturer_Part_Number: RC0603JR-070RL; Manufacturer: YAGEO; Provided_By: SUBCO
TP1 TP2 = MCD-01506: as TP3 on sheet POWER_BOARD
U1 U9 = MCD-00264: Dual bit dual supply bus transceiver; Part_Type: IC; Manufacturer: TEXAS INSTRUMENTS; Provided_By: SUBCO; ECCN_US: EAR99; ECCN_EU: NEC
U2 = MCD-02309: Power Switch, 5V, 0.85A, RDSon 130mOhm max, with active High enable pin and resistor discharge; Part_Type: IC; Part_Preference: Recommended; Manufacturer: TEXAS INSTRUMENTS; Manufacturer_Part_Number: TPS2051CDBVT
U3 = MCD-00649: Common mode filter with ESD protection for USB 2.0 interface; Part_Type: Diode; Manufacturer: STMICROELECTRONICS; BMS_Part_Number: 9151138; Provided_By: SUBCO with ST control; ECCN_US: EAR99; ECCN_EU: NEC
U4 = MCD-00251: High power transient voltage suppressor, 7V breakdown; Part_Type: Diode; Manufacturer: STMICROELECTRONICS; BMS_Part_Number: 9179042; Provided_By: SUBCO with ST control; ECCN_US: EAR99; ECCN_EU: NEC
U5 U7 = MCD-00136: Dual Transil array for ESD protection; Part_Type: Diode; Manufacturer: STMICROELECTRONICS; BMS_Part_Number: 9151112; Provided_By: SUBCO with ST control; ECCN_US: EAR99; ECCN_EU: NEC
U6 = MCD-00596: STM32F723IEK  (STM32F7) BGA176; Part_Type: IC; Manufacturer_Part_Number: STM32F723IEK6; Manufacturer: STMICROELECTRONICS; BMS_Part_Number: 9175300; Provided_By: SUBCO with ST control; ECCN_US: 3A991A2; ECCN_EU: NEC
U8 = MCD-00086: Ultra low drop-low noise BiCMOS voltage, regulators low ESR capacitors compatible; Manufacturer: STMICROELECTRONICS; Part_Type: IC; BMS_Part_Number: 9176161; Provided_By: SUBCO with ST control; ECCN_US: EAR99; ECCN_EU: NEC
X1 = MCD-00597: Oscillator 25Mhz, +-50ppm, Vcc:3.3V typ, square wave: [0.1Vcc;0.9Vcc], Enable pin, SMD; Manufacturer_Part_Number: NZ2520SH 25MHz END4869C; Manufacturer: NDK; Alternate_Manufacturer_Part_Number: NZ2520SB 25MHz END4869B; Part_Type: Crystal_Osc; BMS_Part_Number: 9157050; Provided_By: SUBCO; ECCN_US: EAR99; ECCN_EU: NEC

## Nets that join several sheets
1V8: ARDUINO_extension_connectors (SB16.1), POWER_BOARD (6 pins)
3V3: STM32_microcontroller_IOs (R23.1 R24.1), STM32_microcontroller_power (SB29.1 SB30.1 SB54.1), ARDUINO_extension_connectors (CN8.7 CN11.16 R25.2 SB18.1), USB_Type_C (R36.1 R37.2 U15.12), POWER_BOARD (JP4.1 SB1.2 TP4.1)
5V: ARDUINO_extension_connectors (CN8.9 CN11.18), POWER_BOARD (12 pins), ST_LINK_V3E (R16.1)
5V_EXT: ARDUINO_extension_connectors (CN11.6), POWER_BOARD (JP6.5), ST_LINK_V3E (D3.1)
5V_UCPD: USB_Type_C (7 pins), POWER_BOARD (JP6.7), ST_LINK_V3E (D4.1)
5V_USB_CHGR: POWER_BOARD (JP6.9), ST_LINK_V3E (8 pins)
5V_USB_STLK: ARDUINO_extension_connectors (CN12.8), POWER_BOARD (JP6.1), ST_LINK_V3E (C1.2 TP1.1 U2.1)
5V_VIN: ARDUINO_extension_connectors (R30.2), POWER_BOARD (C42.2 JP6.3 U11.2 U11.4), ST_LINK_V3E (D2.1)
AGND: STM32_microcontroller_power (6 pins), ARDUINO_extension_connectors (C65.1 CN10.3 CN12.32)
GND: STM32_microcontroller_IOs (18 pins), STM32_microcontroller_power (36 pins), ARDUINO_extension_connectors (26 pins), USB_Type_C (22 pins), POWER_BOARD (19 pins), ST_LINK_V3E (109 pins)
VBAT: STM32_microcontroller_power (C77.2 SB50.2 U13.6), ARDUINO_extension_connectors (CN11.33)
VDD: STM32_microcontroller_IOs (B1.1 B1.2), STM32_microcontroller_power (JP5.1), ARDUINO_extension_connectors (CN11.5 SB17.1), POWER_BOARD (JP4.2), ST_LINK_V3E (7 pins)
VDDA: STM32_microcontroller_power (6 pins), ARDUINO_extension_connectors (CN10.1)
VIN: ARDUINO_extension_connectors (CN8.15 CN11.24), POWER_BOARD (C43.2 U11.3)
VREFP: STM32_microcontroller_power (C53.1 C55.2 SB3.2 U13.31), ARDUINO_extension_connectors (C65.2 SB20.2)
ARD_D0_RX: STM32_microcontroller_IOs (SB27.1 SB33.2), ARDUINO_extension_connectors (CN10.16)
ARD_D1_TX: STM32_microcontroller_IOs (SB25.1 SB31.2), ARDUINO_extension_connectors (CN10.14)
NRST: STM32_microcontroller_IOs (5 pins), ARDUINO_extension_connectors (CN8.5 CN11.14)
PA0: STM32_microcontroller_IOs (SB59.2 U13.33), ARDUINO_extension_connectors (CN11.28 SB60.1)
PA1: STM32_microcontroller_IOs (U13.34), ARDUINO_extension_connectors (CN10.11 CN11.30)
PA2: STM32_microcontroller_IOs (U13.35), ARDUINO_extension_connectors (CN12.35 SB56.1 SB57.1)
PA3: STM32_microcontroller_IOs (U13.36), ARDUINO_extension_connectors (CN9.1 CN12.37)
PA4: STM32_microcontroller_IOs (U13.39), ARDUINO_extension_connectors (CN11.32 SB35.1 SB38.1)
PA5: STM32_microcontroller_IOs (U13.40), ARDUINO_extension_connectors (CN7.10 CN12.11 SB23.1)
PA6: STM32_microcontroller_IOs (U13.41), ARDUINO_extension_connectors (CN7.12 CN12.13)
PA7: STM32_microcontroller_IOs (U13.42), ARDUINO_extension_connectors (CN7.14 CN12.15)
PA8: STM32_microcontroller_IOs (U13.100), ARDUINO_extension_connectors (CN10.31 CN12.23)
PA9: STM32_microcontroller_IOs (SB31.1 SB32.1 U13.101), ARDUINO_extension_connectors (CN12.21)
PA10: STM32_microcontroller_IOs (SB33.1 SB34.1 U13.102), ARDUINO_extension_connectors (CN12.33)
PA11: STM32_microcontroller_IOs (SB40.1), ARDUINO_extension_connectors (CN12.14)
PA12: STM32_microcontroller_IOs (SB41.1), ARDUINO_extension_connectors (CN12.12)
PA13: STM32_microcontroller_IOs (U13.105), ARDUINO_extension_connectors (CN11.13), ST_LINK_V3E (CN5.4 R11.1 U7.5)
PA14: STM32_microcontroller_IOs (U13.109), ARDUINO_extension_connectors (CN11.15), ST_LINK_V3E (CN5.6 R12.2 U7.4)
PA15: STM32_microcontroller_IOs (SB39.2 SB42.2 U13.110), ARDUINO_extension_connectors (CN11.17)
PB0: STM32_microcontroller_IOs (U13.43), ARDUINO_extension_connectors (SB63.1 SB64.1 SB65.2)
PB1: STM32_microcontroller_IOs (U13.44), ARDUINO_extension_connectors (CN10.7 CN12.24)
PB2: STM32_microcontroller_IOs (U13.45), ARDUINO_extension_connectors (CN9.13 CN12.22)
PB3: STM32_microcontroller_IOs (SB44.2 U13.132), ARDUINO_extension_connectors (CN7.15 CN12.31)
PB4: STM32_microcontroller_IOs (U13.133), ARDUINO_extension_connectors (CN12.27 SB36.1 SB43.1)
PB5: STM32_microcontroller_IOs (SB46.2 U13.134), ARDUINO_extension_connectors (CN12.29 SB37.1)
PB6: STM32_microcontroller_IOs (U13.135), ARDUINO_extension_connectors (CN9.15 CN12.17)
PB7: STM32_microcontroller_IOs (R50.1 U13.136), ARDUINO_extension_connectors (CN11.21)
PB8: STM32_microcontroller_IOs (U13.138), ARDUINO_extension_connectors (CN7.2 CN12.3)
PB9: STM32_microcontroller_IOs (U13.139), ARDUINO_extension_connectors (CN7.4 CN12.5)
PB10: STM32_microcontroller_IOs (U13.66), ARDUINO_extension_connectors (CN12.25 SB61.1 SB62.2)
PB11: STM32_microcontroller_IOs (U13.67), ARDUINO_extension_connectors (CN10.34 CN12.18)
PB13: STM32_microcontroller_IOs (U13.74), ARDUINO_extension_connectors (CN7.5 CN12.30)
PB14: STM32_microcontroller_IOs (SB45.2 U13.75), ARDUINO_extension_connectors (CN12.28)
PB15: STM32_microcontroller_IOs (U13.76), ARDUINO_extension_connectors (CN12.26), USB_Type_C (C63.2 SB9.1 U15.1)
PC0: STM32_microcontroller_IOs (U13.26), ARDUINO_extension_connectors (CN9.11 CN11.38)
PC1: STM32_microcontroller_IOs (U13.27), ARDUINO_extension_connectors (CN9.9 CN11.36)
PC2: STM32_microcontroller_IOs (SB6.1 U13.28), ARDUINO_extension_connectors (CN11.35 SB53.1)
PC3: STM32_microcontroller_IOs (U13.29), ARDUINO_extension_connectors (CN9.5 CN11.37)
PC6: STM32_microcontroller_IOs (U13.96), ARDUINO_extension_connectors (CN7.1 CN12.4)
PC7: STM32_microcontroller_IOs (U13.97), ARDUINO_extension_connectors (CN12.19 SB21.1)
PC8: STM32_microcontroller_IOs (U13.98), ARDUINO_extension_connectors (CN8.2 SB19.2)
PC9: STM32_microcontroller_IOs (U13.99), ARDUINO_extension_connectors (CN8.4 SB22.1)
PC10: STM32_microcontroller_IOs (U13.111), ARDUINO_extension_connectors (CN8.6 CN11.1)
PC11: STM32_microcontroller_IOs (U13.112), ARDUINO_extension_connectors (CN8.8 CN11.2)
PC12: STM32_microcontroller_IOs (U13.113), ARDUINO_extension_connectors (CN8.10 CN11.3)
PC13: STM32_microcontroller_IOs (SB58.2 U13.7), ARDUINO_extension_connectors (CN11.23)
PC14: STM32_microcontroller_IOs (SB52.2), ARDUINO_extension_connectors (CN11.25)
PC15: STM32_microcontroller_IOs (SB51.2), ARDUINO_extension_connectors (CN11.27)
PD0: STM32_microcontroller_IOs (U13.114), ARDUINO_extension_connectors (CN9.25 CN11.57)
PD1: STM32_microcontroller_IOs (U13.115), ARDUINO_extension_connectors (CN9.27 CN11.55)
PD2: STM32_microcontroller_IOs (U13.116), ARDUINO_extension_connectors (CN8.12 CN11.4)
PD3: STM32_microcontroller_IOs (U13.117), ARDUINO_extension_connectors (CN9.10 CN11.40)
PD4: STM32_microcontroller_IOs (U13.118), ARDUINO_extension_connectors (CN9.8 CN11.39)
PD5: STM32_microcontroller_IOs (U13.119), ARDUINO_extension_connectors (CN9.6 CN11.41)
PD6: STM32_microcontroller_IOs (U13.122), ARDUINO_extension_connectors (CN9.4 CN11.43)
PD7: STM32_microcontroller_IOs (U13.123), ARDUINO_extension_connectors (CN9.2 CN11.45)
PD8: STM32_microcontroller_IOs (U13.77), ARDUINO_extension_connectors (CN12.10)
PD9: STM32_microcontroller_IOs (U13.78), ARDUINO_extension_connectors (CN11.69)
PD10: STM32_microcontroller_IOs (U13.79), ARDUINO_extension_connectors (CN12.65)
PD11: STM32_microcontroller_IOs (U13.80), ARDUINO_extension_connectors (CN7.3 CN12.45)
PD12: STM32_microcontroller_IOs (U13.81), ARDUINO_extension_connectors (CN7.7 CN12.43)
PD13: STM32_microcontroller_IOs (U13.82), ARDUINO_extension_connectors (CN12.41)
PD14: STM32_microcontroller_IOs (U13.85), ARDUINO_extension_connectors (CN7.16 CN12.46)
PD15: STM32_microcontroller_IOs (U13.86), ARDUINO_extension_connectors (CN7.18 CN12.48)
PE0: STM32_microcontroller_IOs (U13.140), ARDUINO_extension_connectors (CN10.33 CN12.64)
PE1: STM32_microcontroller_IOs (U13.141), ARDUINO_extension_connectors (CN11.61)
PE2: STM32_microcontroller_IOs (U13.1), ARDUINO_extension_connectors (CN9.14 CN11.46)
PE3: STM32_microcontroller_IOs (U13.2), ARDUINO_extension_connectors (CN9.22 CN11.47)
PE4: STM32_microcontroller_IOs (U13.3), ARDUINO_extension_connectors (CN9.16 CN11.48)
PE5: STM32_microcontroller_IOs (U13.4), ARDUINO_extension_connectors (CN9.18 CN11.50)
PE6: STM32_microcontroller_IOs (U13.5), ARDUINO_extension_connectors (CN9.20 CN11.62)
PE7: STM32_microcontroller_IOs (U13.55), ARDUINO_extension_connectors (CN10.20 CN12.44)
PE8: STM32_microcontroller_IOs (U13.56), ARDUINO_extension_connectors (CN10.18 CN12.40)
PE9: STM32_microcontroller_IOs (U13.57), ARDUINO_extension_connectors (CN10.4 CN12.52)
PE10: STM32_microcontroller_IOs (U13.60), ARDUINO_extension_connectors (CN10.24 CN12.47)
PE11: STM32_microcontroller_IOs (U13.61), ARDUINO_extension_connectors (CN10.6 CN12.56)
PE12: STM32_microcontroller_IOs (U13.62), ARDUINO_extension_connectors (CN12.49 SB68.1 SB69.2)
PE13: STM32_microcontroller_IOs (U13.63), ARDUINO_extension_connectors (CN10.10 CN12.55)
PE14: STM32_microcontroller_IOs (U13.64), ARDUINO_extension_connectors (CN12.51 SB70.1 SB71.2)
PE15: STM32_microcontroller_IOs (U13.65), ARDUINO_extension_connectors (CN12.53 SB66.1 SB67.2)
PF0: STM32_microcontroller_IOs (U13.10), ARDUINO_extension_connectors (CN9.21 CN11.53)
PF1: STM32_microcontroller_IOs (U13.11), ARDUINO_extension_connectors (CN9.19 CN11.51)
PF2: STM32_microcontroller_IOs (U13.12), ARDUINO_extension_connectors (CN9.17 CN11.52)
PF3: STM32_microcontroller_IOs (U13.13), ARDUINO_extension_connectors (CN8.14 CN12.58)
PF4: STM32_microcontroller_IOs (U13.14), ARDUINO_extension_connectors (CN12.38)
PF5: STM32_microcontroller_IOs (U13.15), ARDUINO_extension_connectors (CN8.16 CN12.36)
PF6: STM32_microcontroller_IOs (U13.18), ARDUINO_extension_connectors (CN11.9)
PF7: STM32_microcontroller_IOs (U13.19), ARDUINO_extension_connectors (CN9.26 CN11.11)
PF8: STM32_microcontroller_IOs (U13.20), ARDUINO_extension_connectors (CN9.24 CN11.54)
PF9: STM32_microcontroller_IOs (U13.21), ARDUINO_extension_connectors (CN9.28 CN11.56)
PF10: STM32_microcontroller_IOs (U13.22), ARDUINO_extension_connectors (CN12.42)
PF11: STM32_microcontroller_IOs (U13.46), ARDUINO_extension_connectors (CN12.62)
PF12: STM32_microcontroller_IOs (U13.47), ARDUINO_extension_connectors (CN7.20 CN12.59)
PF13: STM32_microcontroller_IOs (U13.50), ARDUINO_extension_connectors (CN10.2 CN12.57)
PF14: STM32_microcontroller_IOs (U13.51), ARDUINO_extension_connectors (CN10.8 CN12.50)
PF15: STM32_microcontroller_IOs (U13.52), ARDUINO_extension_connectors (CN10.12 CN12.60)
PG0: STM32_microcontroller_IOs (U13.53), ARDUINO_extension_connectors (CN9.29 CN11.59)
PG1: STM32_microcontroller_IOs (U13.54), ARDUINO_extension_connectors (CN9.30 CN11.58)
PG2: STM32_microcontroller_IOs (R51.1 U13.87), ARDUINO_extension_connectors (CN11.42)
PG3: STM32_microcontroller_IOs (U13.88), ARDUINO_extension_connectors (CN11.44)
PG4: STM32_microcontroller_IOs (U13.89), ARDUINO_extension_connectors (CN12.69)
PG5: STM32_microcontroller_IOs (U13.90), ARDUINO_extension_connectors (CN12.68)
PG6: STM32_microcontroller_IOs (U13.91), ARDUINO_extension_connectors (CN12.70)
PG7: STM32_microcontroller_IOs (SB24.2 SB25.2 U13.92), ARDUINO_extension_connectors (SB73.1)
PG8: STM32_microcontroller_IOs (SB26.2 SB27.2 U13.93), ARDUINO_extension_connectors (SB72.2)
PG9: STM32_microcontroller_IOs (U13.124), ARDUINO_extension_connectors (CN11.63)
PG10: STM32_microcontroller_IOs (U13.125), ARDUINO_extension_connectors (CN11.66)
PG12: STM32_microcontroller_IOs (U13.126), ARDUINO_extension_connectors (CN11.65)
PG13: STM32_microcontroller_IOs (U13.127), ARDUINO_extension_connectors (CN11.68)
PG14: STM32_microcontroller_IOs (U13.128), ARDUINO_extension_connectors (CN12.61)
PG15: STM32_microcontroller_IOs (U13.131), ARDUINO_extension_connectors (CN11.64)
PH0: STM32_microcontroller_IOs (SB47.2), ARDUINO_extension_connectors (CN11.29)
PH1: STM32_microcontroller_IOs (SB49.2), ARDUINO_extension_connectors (CN11.31)
PH3-BOOT0: STM32_microcontroller_IOs (R31.1 U13.137), ARDUINO_extension_connectors (CN11.7)
STLK_MCO: STM32_microcontroller_IOs (SB48.2), ST_LINK_V3E (C5.2 R5.2)
T_JTDI: STM32_microcontroller_IOs (SB39.1), ST_LINK_V3E (CN5.10 U7.1)
T_SWO: STM32_microcontroller_IOs (SB44.1), ST_LINK_V3E (CN5.8 R13.1 U7.3)
T_VCP_RX: STM32_microcontroller_IOs (SB26.1 SB34.2), ST_LINK_V3E (CN5.13 R10.2 U5.1)
T_VCP_TX: STM32_microcontroller_IOs (SB24.1 SB32.2), ST_LINK_V3E (CN5.14 R3.1 U5.3)
UCPD_CC1: STM32_microcontroller_IOs (SB42.1), USB_Type_C (C62.2 SB8.1 U15.3)
UCPD_DBn: STM32_microcontroller_IOs (SB46.1), USB_Type_C (JP8.1 U15.10)
UCPD_FLT: STM32_microcontroller_IOs (SB45.1), USB_Type_C (JP7.1 R37.1 U15.11)
USB_FS_N: STM32_microcontroller_IOs (SB40.2 U13.103), USB_Type_C (CN15.A7 CN15.B7 U14.1 U14.6)
USB_FS_P: STM32_microcontroller_IOs (SB41.2 U13.104), USB_Type_C (CN15.A6 CN15.B6 U14.3 U14.4)
VBUS_SENSE: STM32_microcontroller_IOs (SB6.2), USB_Type_C (C61.2 R34.2 R35.1)

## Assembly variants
U575ZIQ: not fitted C48 C49 C50 C59 C60 C82 CN2 CN11 CN12 HW11 R5 R27 R29 R44 R48 R52 SB4 SB5 SB8 SB9 SB10 SB11 SB12 SB14 SB15 SB16 SB18 SB20 SB23 SB24 SB26 SB29 SB31 SB33 SB39 SB40 SB41 SB48 SB51 SB52 SB54 SB59 U19 X3
U575ZIQ_S: not fitted C48 C49 C50 C82 CN2 CN11 CN12 R5 R27 R29 R44 R48 R52 SB8 SB9 SB10 SB11 SB12 SB14 SB15 SB16 SB18 SB20 SB23 SB24 SB26 SB29 SB31 SB33 SB39 SB40 SB41 SB48 SB51 SB52 SB54 SB59 U19
U595ZJQ: not fitted C48 C49 C50 C82 CN2 CN11 CN12 HW11 R5 R27 R29 R44 R48 R52 SB8 SB9 SB10 SB11 SB12 SB14 SB15 SB16 SB18 SB20 SB23 SB24 SB26 SB29 SB31 SB33 SB39 SB40 SB41 SB47 SB48 SB49 SB51 SB52 SB54 SB59 U19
